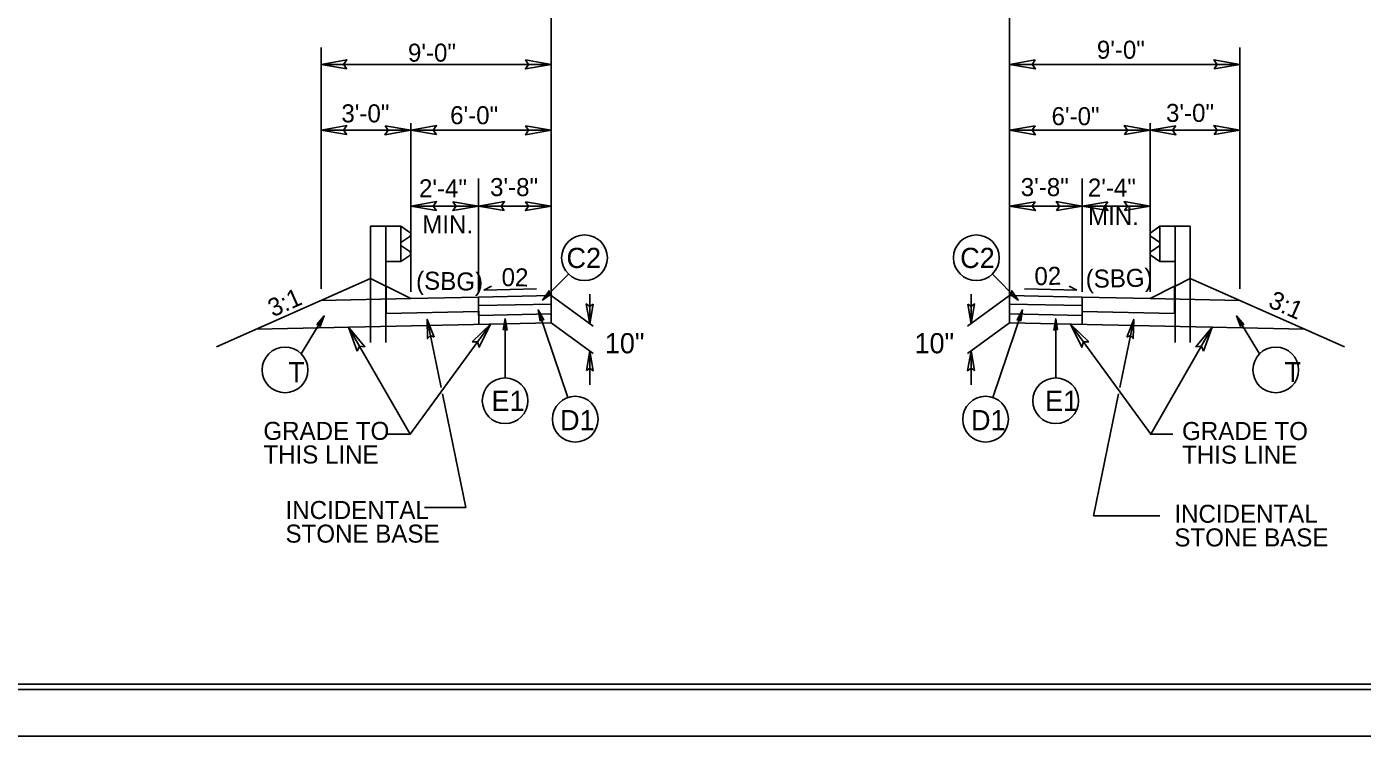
# Model space of a CAD drawing. Extents: x 1804008 to 1804260, y 659269 to 659379.
# Drawn here: x 1804134.6 to 1804198.7, y 659269.4 to 659303.4 of the extents above; entities that cross this region are included whole.
import ezdxf

# ---------------------------------------------------------------- set-up
doc = ezdxf.new("R2010")
doc.units = 0
for name, color, linetype in [('Default', 7, 'Continuous'), ('Old_Level_1', 7, 'Continuous'), ('Old_Level_11', 7, 'Continuous'), ('Old_Level_2', 7, 'Continuous'), ('Old_Level_3', 7, 'Continuous'), ('Prop Dimension', 7, 'Continuous'), ('Prop Pavement Schedule Description CELL', 7, 'Continuous'), ('Prop Terminator CELL', 7, 'Continuous'), ('Sheet Cutting Line CELL', 7, 'Continuous'), ('Sheet Plot Border Inside CELL', 7, 'Continuous'), ('Sheet Plot Border Outside CELL', 7, 'Continuous'), ('Sheet Typical CELL', 7, 'Continuous'), ('Typical Guardrail CELL', 7, 'Continuous'), ('Typical ID Circle CELL', 7, 'Continuous'), ('Typical Terminator CELL', 7, 'Continuous'), ('Typical Text ID Circle CELL', 7, 'Continuous')]:
    doc.layers.add(name, color=color, linetype=linetype)

msp = doc.modelspace()

# ---------------------------------------------------------------- linework, layer by layer
at = {"layer": 'Default'}
for p, q in [((1804148.745, 659302.41), (1804148.745, 659290.825)), ((1804192.835, 659302.41), (1804192.835, 659290.825)), ((1804153.052, 659298.776), (1804153.052, 659290.681)), ((1804188.527, 659298.776), (1804188.527, 659290.681)), ((1804156.309, 659296.123), (1804156.309, 659290.681)), ((1804185.27, 659296.123), (1804185.27, 659290.681))]:
    msp.add_line(p, q, dxfattribs=at)
at = {"layer": 'Old_Level_1'}
for p, q in [((1804159.79, 659320.87), (1804159.79, 659289.984)), ((1804181.79, 659320.86), (1804181.79, 659290.502)), ((1804151.125, 659291.324), (1804143.722, 659288.039)), ((1804151.125, 659291.324), (1804151.852, 659290.96)), ((1804151.125, 659291.324), (1804151.125, 659290.196)), ((1804190.454, 659291.324), (1804189.727, 659290.96)), ((1804190.454, 659291.324), (1804197.857, 659288.039)), ((1804190.454, 659291.324), (1804190.454, 659290.196)), ((1804151.852, 659290.96), (1804151.852, 659290.196)), ((1804151.87, 659290.951), (1804153.052, 659290.36)), ((1804151.87, 659289.644), (1804151.87, 659290.951)), ((1804156.566, 659290.77), (1804156.929, 659290.953)), ((1804159.083, 659290.823), (1804156.566, 659290.77)), ((1804182.496, 659290.823), (1804185.014, 659290.77)), ((1804185.014, 659290.77), (1804184.65, 659290.953)), ((1804189.709, 659290.951), (1804188.527, 659290.36)), ((1804189.709, 659289.644), (1804189.709, 659290.951)), ((1804189.727, 659290.96), (1804189.727, 659290.196)), ((1804153.052, 659290.36), (1804148.745, 659290.268)), ((1804153.052, 659290.36), (1804156.309, 659290.43)), ((1804156.309, 659290.43), (1804156.31, 659289.551)), ((1804185.27, 659290.43), (1804185.269, 659289.551)), ((1804188.527, 659290.36), (1804185.27, 659290.43)), ((1804188.527, 659290.36), (1804192.835, 659290.268)), ((1804156.31, 659289.739), (1804151.87, 659289.644)), ((1804185.269, 659289.739), (1804189.709, 659289.644))]:
    msp.add_line(p, q, dxfattribs=at)
at = {"layer": 'Old_Level_11'}
for p, q in [((1804159.79, 659301.603), (1804148.745, 659301.603)), ((1804181.79, 659301.603), (1804192.835, 659301.603)), ((1804153.052, 659298.447), (1804148.745, 659298.447)), ((1804159.79, 659298.447), (1804153.052, 659298.447)), ((1804181.79, 659298.447), (1804188.527, 659298.447)), ((1804188.527, 659298.447), (1804192.835, 659298.447)), ((1804156.309, 659294.801), (1804153.052, 659294.801)), ((1804159.79, 659294.801), (1804156.309, 659294.801)), ((1804181.79, 659294.801), (1804185.27, 659294.801)), ((1804185.27, 659294.801), (1804188.527, 659294.801)), ((1804153.836, 659289.362), (1804154.507, 659286.09)), ((1804187.743, 659289.362), (1804187.073, 659286.09)), ((1804156.871, 659289.131), (1804153.016, 659283.853)), ((1804184.708, 659289.131), (1804188.563, 659283.853)), ((1804154.57, 659285.782), (1804155.688, 659280.327)), ((1804187.009, 659285.782), (1804185.812, 659279.941)), ((1804155.688, 659280.327), (1804153.711, 659280.327)), ((1804185.812, 659279.941), (1804189.005, 659279.941))]:
    msp.add_line(p, q, dxfattribs=at)
for points in [[(1804161.802, 659290.098), (1804161.64, 659289.156), (1804161.473, 659290.103), (1804161.64, 659289.982)], [(1804179.777, 659290.098), (1804179.939, 659289.156), (1804180.107, 659290.103), (1804179.939, 659289.982)], [(1804161.478, 659286.905), (1804161.64, 659287.846), (1804161.807, 659286.9), (1804161.64, 659287.02)], [(1804180.102, 659286.905), (1804179.939, 659287.846), (1804179.772, 659286.9), (1804179.939, 659287.02)]]:
    msp.add_lwpolyline(points, close=True, dxfattribs=at)
for points in [[(1804150.063, 659288.991), (1804153.016, 659283.853), (1804151.958, 659283.853)], [(1804191.516, 659288.991), (1804188.563, 659283.853), (1804189.621, 659283.853)]]:
    msp.add_lwpolyline(points, dxfattribs=at)
at = {"layer": 'Old_Level_2'}
for p, q in [((1804156.309, 659290.43), (1804159.79, 659290.502)), ((1804156.309, 659290.43), (1804156.311, 659289.12)), ((1804156.318, 659290.023), (1804159.798, 659290.096)), ((1804185.261, 659290.023), (1804181.781, 659290.096)), ((1804185.27, 659290.43), (1804181.79, 659290.502)), ((1804185.27, 659290.43), (1804185.269, 659289.12)), ((1804156.31, 659289.551), (1804159.796, 659289.623)), ((1804185.269, 659289.551), (1804181.783, 659289.623))]:
    msp.add_line(p, q, dxfattribs=at)
for points in [[(1804159.79, 659290.502), (1804159.79, 659289.191), (1804145.647, 659288.901)], [(1804181.79, 659290.502), (1804181.79, 659289.191), (1804195.932, 659288.901)]]:
    msp.add_lwpolyline(points, dxfattribs=at)
at = {"layer": 'Prop Dimension'}
for p, q in [((1804159.789, 659290.502), (1804161.807, 659289.035)), ((1804161.64, 659289.156), (1804161.64, 659290.58)), ((1804181.791, 659290.502), (1804179.772, 659289.035)), ((1804179.939, 659289.156), (1804179.939, 659290.58)), ((1804159.79, 659289.191), (1804161.807, 659287.725)), ((1804181.79, 659289.191), (1804179.772, 659287.725)), ((1804161.64, 659286.224), (1804161.64, 659287.846)), ((1804179.939, 659286.224), (1804179.939, 659287.846))]:
    msp.add_line(p, q, dxfattribs=at)
at = {"layer": 'Prop Terminator CELL'}
for points in [[(1804149.977, 659301.39), (1804148.745, 659301.603), (1804149.983, 659301.822), (1804149.826, 659301.603)], [(1804158.558, 659301.815), (1804159.79, 659301.603), (1804158.551, 659301.384), (1804158.708, 659301.603)], [(1804183.022, 659301.815), (1804181.79, 659301.603), (1804183.028, 659301.384), (1804182.871, 659301.603)], [(1804191.603, 659301.39), (1804192.835, 659301.603), (1804191.596, 659301.822), (1804191.753, 659301.603)], [(1804149.977, 659298.234), (1804148.745, 659298.447), (1804149.983, 659298.666), (1804149.826, 659298.447)], [(1804151.82, 659298.659), (1804153.052, 659298.447), (1804151.813, 659298.228), (1804151.971, 659298.447)], [(1804154.284, 659298.234), (1804153.052, 659298.447), (1804154.291, 659298.666), (1804154.134, 659298.447)], [(1804158.558, 659298.659), (1804159.79, 659298.447), (1804158.551, 659298.228), (1804158.708, 659298.447)], [(1804183.022, 659298.659), (1804181.79, 659298.447), (1804183.028, 659298.228), (1804182.871, 659298.447)], [(1804187.295, 659298.234), (1804188.527, 659298.447), (1804187.288, 659298.666), (1804187.445, 659298.447)], [(1804189.759, 659298.659), (1804188.527, 659298.447), (1804189.766, 659298.228), (1804189.608, 659298.447)], [(1804191.603, 659298.234), (1804192.835, 659298.447), (1804191.596, 659298.666), (1804191.753, 659298.447)], [(1804154.284, 659294.589), (1804153.052, 659294.801), (1804154.291, 659295.02), (1804154.134, 659294.801)], [(1804155.077, 659295.013), (1804156.309, 659294.801), (1804155.071, 659294.582), (1804155.228, 659294.801)], [(1804157.541, 659294.589), (1804156.309, 659294.801), (1804157.548, 659295.02), (1804157.391, 659294.801)], [(1804158.558, 659295.013), (1804159.79, 659294.801), (1804158.551, 659294.582), (1804158.708, 659294.801)], [(1804183.022, 659295.013), (1804181.79, 659294.801), (1804183.028, 659294.582), (1804182.871, 659294.801)], [(1804184.038, 659294.589), (1804185.27, 659294.801), (1804184.031, 659295.02), (1804184.188, 659294.801)], [(1804186.502, 659295.013), (1804185.27, 659294.801), (1804186.509, 659294.582), (1804186.351, 659294.801)], [(1804187.295, 659294.589), (1804188.527, 659294.801), (1804187.288, 659295.02), (1804187.445, 659294.801)], [(1804154.169, 659288.511), (1804153.836, 659289.362), (1804153.861, 659288.443), (1804153.995, 659288.588)], [(1804187.411, 659288.511), (1804187.743, 659289.362), (1804187.718, 659288.443), (1804187.585, 659288.588)]]:
    msp.add_lwpolyline(points, close=True, dxfattribs=at)
at = {"layer": 'Sheet Cutting Line CELL'}
msp.add_line((1804067.894, 659269.353), (1804236.294, 659269.353), dxfattribs=at)
at = {"layer": 'Sheet Plot Border Inside CELL'}
msp.add_lwpolyline([(1804235.844, 659377.108), (1804069.194, 659377.108), (1804069.194, 659271.598), (1804235.844, 659271.598)], close=True, dxfattribs=at)
at = {"layer": 'Sheet Plot Border Outside CELL'}
msp.add_lwpolyline([(1804236.294, 659379.353), (1804067.894, 659379.353), (1804067.894, 659269.353), (1804236.294, 659269.353)], close=True, dxfattribs=at)
at = {"layer": 'Sheet Typical CELL'}
msp.add_lwpolyline([(1804234.594, 659376.853), (1804084.594, 659376.853), (1804084.594, 659271.853), (1804234.594, 659271.853)], close=True, dxfattribs=at)
at = {"layer": 'Typical Guardrail CELL'}
for p, q in [((1804151.852, 659293.832), (1804151.125, 659293.832)), ((1804151.125, 659293.832), (1804151.125, 659291.324)), ((1804151.852, 659293.832), (1804151.852, 659290.96)), ((1804151.852, 659293.832), (1804152.58, 659293.832)), ((1804152.58, 659293.832), (1804152.58, 659292.136)), ((1804152.58, 659293.832), (1804153.003, 659293.535)), ((1804152.58, 659293.052), (1804153.003, 659293.349)), ((1804188.999, 659293.832), (1804188.576, 659293.535)), ((1804188.999, 659293.052), (1804188.576, 659293.349)), ((1804189.727, 659293.832), (1804188.999, 659293.832)), ((1804188.999, 659293.832), (1804188.999, 659292.136)), ((1804189.727, 659293.832), (1804189.727, 659290.96)), ((1804189.727, 659293.832), (1804190.454, 659293.832)), ((1804190.454, 659293.832), (1804190.454, 659291.324)), ((1804152.58, 659292.984), (1804152.58, 659293.052)), ((1804152.58, 659292.984), (1804152.58, 659292.916)), ((1804152.58, 659292.916), (1804153.003, 659292.619)), ((1804188.999, 659292.916), (1804188.576, 659292.619)), ((1804188.999, 659292.984), (1804188.999, 659293.052)), ((1804188.999, 659292.984), (1804188.999, 659292.916)), ((1804151.852, 659292.136), (1804152.58, 659292.136)), ((1804152.58, 659292.136), (1804153.003, 659292.432)), ((1804188.999, 659292.136), (1804188.576, 659292.432)), ((1804189.727, 659292.136), (1804188.999, 659292.136)), ((1804151.125, 659290.196), (1804151.125, 659288.252)), ((1804151.852, 659290.196), (1804151.852, 659288.252)), ((1804189.727, 659290.196), (1804189.727, 659288.252)), ((1804190.454, 659290.196), (1804190.454, 659288.252))]:
    msp.add_line(p, q, dxfattribs=at)
for centre, start, end in [((1804152.939, 659293.442), 304.9888, 54.99703), ((1804188.64, 659293.442), 125.00297, 235.0112), ((1804152.939, 659292.526), 304.9634, 54.9941), ((1804188.641, 659292.526), 125.0059, 235.0366)]:
    msp.add_arc(centre, 0.114, start, end, dxfattribs=at)
at = {"layer": 'Typical ID Circle CELL'}
for p, q in [((1804160.617, 659291.541), (1804159.376, 659290.289)), ((1804180.963, 659291.541), (1804182.203, 659290.289)), ((1804147.794, 659287.713), (1804148.903, 659289.531)), ((1804157.577, 659286.555), (1804157.577, 659289.391)), ((1804160.593, 659285.613), (1804159.173, 659289.82)), ((1804180.986, 659285.613), (1804182.406, 659289.82)), ((1804184.002, 659286.555), (1804184.002, 659289.391)), ((1804193.785, 659287.713), (1804192.677, 659289.531))]:
    msp.add_line(p, q, dxfattribs=at)
for centre in [(1804161.389, 659292.32), (1804180.19, 659292.32), (1804147.018, 659286.937), (1804194.561, 659286.937), (1804157.577, 659285.459), (1804184.002, 659285.459), (1804160.944, 659284.573), (1804180.635, 659284.573)]:
    msp.add_circle(centre, 1.097, dxfattribs=at)
at = {"layer": 'Typical Terminator CELL'}
for points in [[(1804159.818, 659290.604), (1804159.376, 659290.289), (1804159.687, 659290.738), (1804159.706, 659290.623)], [(1804181.761, 659290.604), (1804182.203, 659290.289), (1804181.892, 659290.738), (1804181.873, 659290.623)], [(1804148.545, 659289.123), (1804148.903, 659289.531), (1804148.703, 659289.023), (1804148.658, 659289.131)], [(1804157.485, 659288.856), (1804157.577, 659289.391), (1804157.672, 659288.853), (1804157.577, 659288.921)], [(1804159.257, 659289.284), (1804159.173, 659289.82), (1804159.435, 659289.341), (1804159.323, 659289.375)], [(1804182.322, 659289.284), (1804182.406, 659289.82), (1804182.144, 659289.341), (1804182.256, 659289.375)], [(1804184.094, 659288.856), (1804184.002, 659289.391), (1804183.907, 659288.853), (1804184.002, 659288.921)], [(1804193.034, 659289.123), (1804192.677, 659289.531), (1804192.876, 659289.023), (1804192.921, 659289.131)], [(1804150.483, 659287.845), (1804150.063, 659288.991), (1804150.851, 659288.049), (1804150.589, 659288.076)], [(1804155.994, 659288.282), (1804156.871, 659289.131), (1804156.33, 659288.028), (1804156.248, 659288.278)], [(1804185.585, 659288.282), (1804184.708, 659289.131), (1804185.249, 659288.028), (1804185.331, 659288.278)], [(1804191.096, 659287.845), (1804191.516, 659288.991), (1804190.728, 659288.049), (1804190.99, 659288.076)]]:
    msp.add_lwpolyline(points, close=True, dxfattribs=at)

# ---------------------------------------------------------------- texts
at = {"layer": 'Old_Level_1'}
for s, p in [('9\'-0" ', (1804152.918, 659301.733)), ('9\'-0" ', (1804185.976, 659301.874)), ('3\'-0"', (1804149.723, 659298.819)), ('6\'-0" ', (1804154.942, 659298.73)), ('2\'-4"', (1804153.446, 659295.222)), ('3\'-8"', (1804156.858, 659295.281)), ('2\'-4"', (1804185.545, 659295.257)), ('MIN.', (1804185.552, 659293.891)), ('MIN.', (1804153.601, 659293.493))]:
    msp.add_text(s, height=0.865, dxfattribs=at).set_placement(p)
for s, rotation, p in [('3\'-0"', 360, (1804189.295, 659298.842)), ('6\'-0" ', 360, (1804183.801, 659298.685)), ('3\'-8"', 360, (1804182.324, 659295.281)), ('3:1', 23.7928, (1804146.436, 659289.458)), ('3:1', 336.2072, (1804194.148, 659289.979))]:
    msp.add_text(s, height=0.865, rotation=rotation, dxfattribs=at).set_placement(p)
at = {"layer": 'Old_Level_2'}
for s, rotation, p in [('(SBG)', 358.80842, (1804153.301, 659290.802)), ('02', 358.80842, (1804157.402, 659290.966)), ('02', 1.19158, (1804182.988, 659291.002)), ('(SBG)', 1.19158, (1804185.447, 659290.872))]:
    msp.add_text(s, height=0.865, rotation=rotation, dxfattribs=at).set_placement(p)
at = {"layer": 'Old_Level_3'}
for s, p in [('GRADE TO', (1804145.98, 659283.58)), ('GRADE TO', (1804190.064, 659283.573)), ('THIS LINE', (1804145.98, 659282.446)), ('THIS LINE', (1804190.064, 659282.439)), ('INCIDENTAL', (1804147.042, 659279.782)), ('INCIDENTAL', (1804189.696, 659279.6)), ('STONE BASE', (1804147.042, 659278.648)), ('STONE BASE', (1804189.696, 659278.466))]:
    msp.add_text(s, height=0.865, dxfattribs=at).set_placement(p)
at = {"layer": 'Prop Pavement Schedule Description CELL'}
for p in [(1804162.366, 659287.734), (1804177.226, 659287.734)]:
    msp.add_text('10"', height=0.9691, dxfattribs=at).set_placement(p)
at = {"layer": 'Typical Text ID Circle CELL'}
for s, height, p in [('C2', 0.9691, (1804160.526, 659291.829)), ('C2', 0.9691, (1804179.418, 659291.829)), ('T', 0.969, (1804147.172, 659286.343)), ('E1', 0.9691, (1804156.926, 659284.968)), ('E1', 0.9691, (1804183.49, 659284.968)), ('D1', 0.9691, (1804160.217, 659284.043)), ('D1', 0.9691, (1804179.937, 659284.043))]:
    msp.add_text(s, height=height, dxfattribs=at).set_placement(p)
msp.add_text('T', height=0.969, rotation=360, dxfattribs=at).set_placement((1804194.983, 659286.352))

doc.saveas('drawing.dxf')
